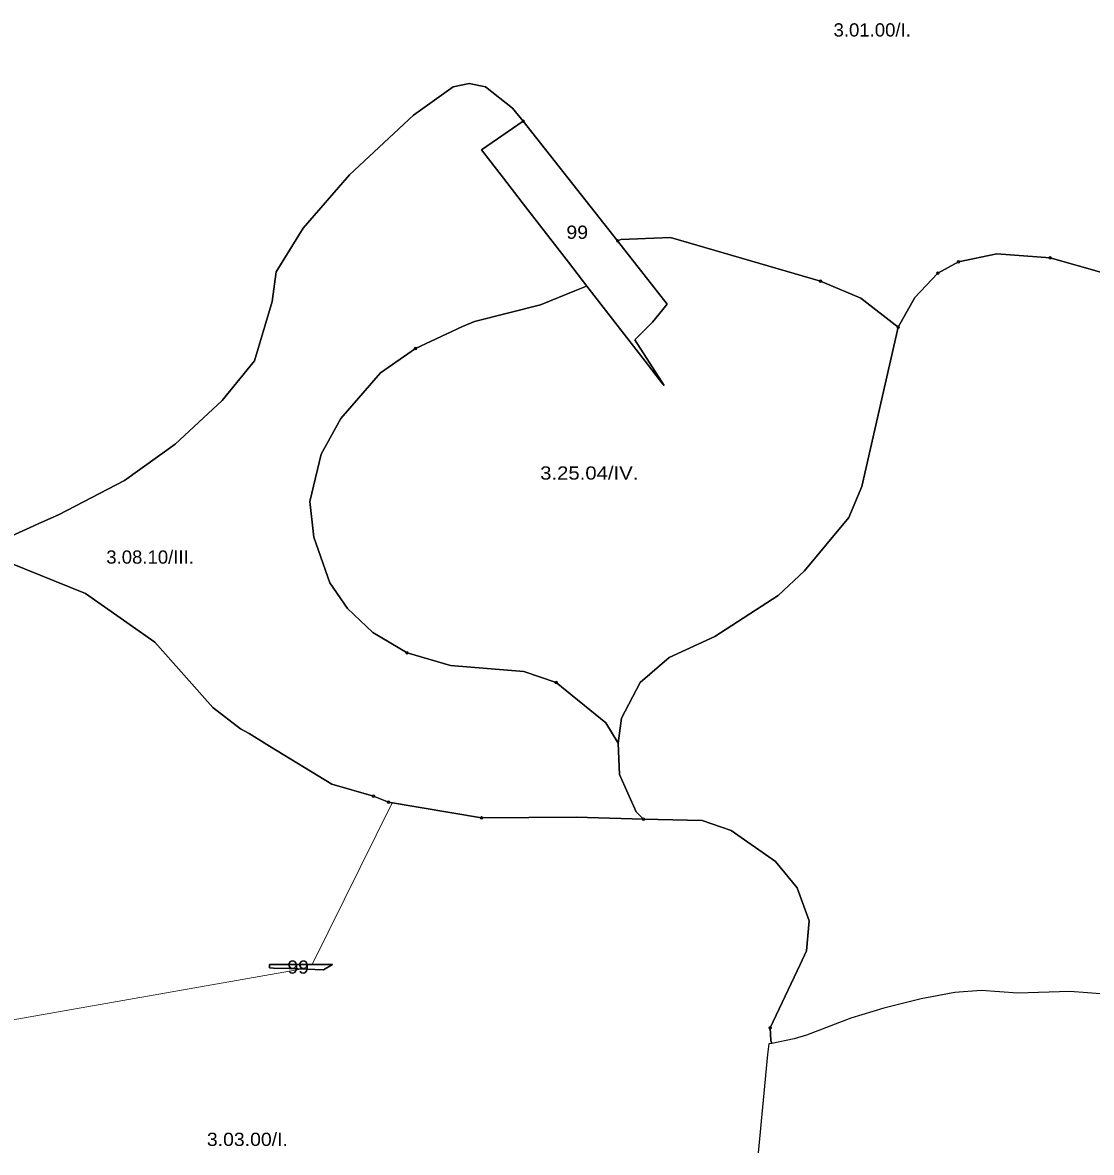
# Model space of a CAD drawing. Extents: x -650455 to -642254, y -1075222 to -1066610.
# Drawn here: x -647687 to -646878, y -1073142 to -1072287 of the extents above; entities that cross this region are included whole.
import ezdxf
from ezdxf.enums import TextEntityAlignment as Align

# ---------------------------------------------------------------- set-up
doc = ezdxf.new("R2010")
doc.units = 0
doc.header["$LTSCALE"] = 4
doc.header["$PDMODE"] = 32
doc.header["$PDSIZE"] = 2
for name, color, linetype, lineweight in [('1', 7, 'Continuous', 25), ('11', 7, 'Continuous', 13), ('13', 7, 'Continuous', 13), ('14', 7, 'Continuous', 13)]:
    doc.layers.add(name, color=color, linetype=linetype, lineweight=lineweight)
doc.layers.add('2', color=7, linetype='Continuous')

msp = doc.modelspace()

# ---------------------------------------------------------------- linework, layer by layer
at = {"layer": '1'}
for points in [[(-647639.5, -1072719.001), (-647697.5, -1072695.5), (-647728.952, -1072689.256), (-647713.137, -1072683.505), (-647698.521, -1072676.851), (-647672.5, -1072665), (-647660, -1072659.5), (-647610, -1072633.501), (-647571.5, -1072606.001), (-647536, -1072573.001), (-647511.5, -1072543), (-647500, -1072504.667), (-647498, -1072498), (-647495, -1072475.501), (-647474.5, -1072442.501), (-647439.5, -1072402.001), (-647391, -1072357), (-647361, -1072335.5), (-647349, -1072333), (-647336.5, -1072335.5), (-647316, -1072351.5), (-647308, -1072361.501)], [(-646870, -1072476.001), (-646909, -1072465), (-646949.5, -1072462), (-646978.5, -1072468.001), (-646994, -1072476.501), (-647011.5, -1072495), (-647024, -1072517.5), (-647052.5, -1072495.501), (-647083, -1072482.5), (-647196.5, -1072449.5), (-647234, -1072451.001), (-647236.5, -1072452.001), (-647308, -1072361.501), (-647316, -1072351.5), (-647336.5, -1072335.5), (-647349, -1072333), (-647361, -1072335.5), (-647391, -1072357), (-647439.5, -1072402.001), (-647474.5, -1072442.501), (-647495, -1072475.501), (-647498, -1072498), (-647500, -1072504.667), (-647511.5, -1072543), (-647536, -1072573.001), (-647571.5, -1072606.001), (-647610, -1072633.501), (-647660, -1072659.5), (-647672.5, -1072665)], [(-647308, -1072361.501), (-647339.712, -1072383.178), (-647323.06, -1072404.651), (-647306.23, -1072426.351), (-647273.75, -1072468.221), (-647259.75, -1072486.28), (-647259.98, -1072486.34), (-647269, -1072490), (-647295, -1072500.501), (-647345, -1072513.001), (-647354, -1072517.001), (-647389.5, -1072533.5), (-647416, -1072552.001), (-647446, -1072586.5), (-647461, -1072613.501), (-647469.5, -1072649.501), (-647466.5, -1072676.5), (-647454.5, -1072711.001), (-647441, -1072730.501), (-647422, -1072748.5), (-647396, -1072764.001), (-647363, -1072773.5), (-647307.5, -1072778), (-647283, -1072786.5), (-647245.5, -1072817), (-647236, -1072832.501), (-647235, -1072856.001), (-647222.5, -1072884.501), (-647217, -1072890), (-647268, -1072888.501), (-647339.5, -1072889.001), (-647410, -1072877.001), (-647421.34, -1072872.531), (-647453, -1072863.5), (-647500, -1072834.548), (-647515.5, -1072825), (-647522, -1072821.5), (-647543, -1072805.5), (-647587, -1072756.001), (-647639.5, -1072719.001)], [(-647024, -1072517.5), (-647051.5, -1072638.001), (-647061.5, -1072661.501), (-647095, -1072702.001), (-647115, -1072720.5), (-647163, -1072751.501), (-647197.5, -1072767.501), (-647219.5, -1072786.5), (-647233.5, -1072813.5), (-647236, -1072832.501), (-647245.5, -1072817), (-647283, -1072786.5), (-647307.5, -1072778), (-647363, -1072773.5), (-647396, -1072764.001), (-647422, -1072748.5), (-647441, -1072730.501), (-647454.5, -1072711.001), (-647466.5, -1072676.5), (-647469.5, -1072649.501), (-647461, -1072613.501), (-647446, -1072586.5), (-647416, -1072552.001), (-647389.5, -1072533.5), (-647354, -1072517.001), (-647345, -1072513.001), (-647295, -1072500.501), (-647269, -1072490), (-647259.98, -1072486.34), (-647259.75, -1072486.28), (-647217.32, -1072540.99), (-647215.71, -1072543.071), (-647202.22, -1072560.471), (-647201.29, -1072561.671), (-647223.5, -1072527), (-647210, -1072513.5), (-647199, -1072500.001), (-647236.5, -1072452.001), (-647234, -1072451.001), (-647196.5, -1072449.5)], [(-647196.5, -1072449.5), (-647083, -1072482.5), (-647052.5, -1072495.501), (-647024, -1072517.5)], [(-647197.5, -1072767.501), (-647163, -1072751.501), (-647115, -1072720.5), (-647095, -1072702.001), (-647061.5, -1072661.501), (-647051.5, -1072638.001), (-647024, -1072517.5), (-647011.5, -1072495), (-646994, -1072476.501), (-646978.5, -1072468.001), (-646949.5, -1072462), (-646909, -1072465), (-646870, -1072476.001), (-646796, -1072525.5), (-646755, -1072562), (-646671, -1072656.5), (-646615.5, -1072728.5), (-646581.5, -1072768.5), (-646545.5, -1072791.001), (-646519.5, -1072800.501)], [(-647672.5, -1072665), (-647698.521, -1072676.851)], [(-647904.5, -1073148.001), (-647889.5, -1073048.5), (-647885.418, -1073000), (-647881, -1072947.5), (-647868, -1072828.501), (-647861.5, -1072813), (-647845.5, -1072785), (-647801.5, -1072733.5), (-647763.5, -1072702.001), (-647731, -1072690.001), (-647728.952, -1072689.256), (-647697.5, -1072695.5), (-647639.5, -1072719.001), (-647587, -1072756.001), (-647543, -1072805.5), (-647522, -1072821.5), (-647515.5, -1072825), (-647500, -1072834.548), (-647453, -1072863.5), (-647421.34, -1072872.531), (-647410, -1072877.001), (-647339.5, -1072889.001)], [(-646867.497, -1073022.31), (-646894.212, -1073020.321), (-646933.434, -1073021.742), (-646961.287, -1073019.609), (-646981.181, -1073021.173), (-647006.761, -1073025.862), (-647034.898, -1073032.967), (-647060.05, -1073040.642), (-647093.445, -1073053.573), (-647102.824, -1073056.274), (-647119.798, -1073059.69), (-647120.5, -1073057.5), (-647121, -1073048), (-647098.436, -1073000), (-647093.5, -1072989.501), (-647091.5, -1072967), (-647100.5, -1072942.001), (-647117, -1072922.001), (-647150.5, -1072898.5), (-647172.5, -1072891), (-647217, -1072890), (-647222.5, -1072884.501), (-647235, -1072856.001), (-647236, -1072832.501), (-647233.5, -1072813.5), (-647219.5, -1072786.5), (-647197.5, -1072767.501)], [(-647339.5, -1072889.001), (-647268, -1072888.501), (-647217, -1072890)], [(-647217, -1072890), (-647172.5, -1072891), (-647150.5, -1072898.5), (-647117, -1072922.001), (-647100.5, -1072942.001), (-647091.5, -1072967), (-647093.5, -1072989.501), (-647098.436, -1073000), (-647121, -1073048), (-647120.5, -1073057.5), (-647119.798, -1073059.69), (-647121.913, -1073060.116), (-647122.941, -1073068.189), (-647130.088, -1073142.652)]]:
    msp.add_lwpolyline(points, dxfattribs=at)
for points in [[(-647236.5, -1072452.001), (-647199, -1072500.001), (-647210, -1072513.5), (-647223.5, -1072527), (-647201.29, -1072561.671), (-647202.22, -1072560.471), (-647215.71, -1072543.071), (-647217.32, -1072540.99), (-647259.75, -1072486.28), (-647273.75, -1072468.221), (-647306.23, -1072426.351), (-647323.06, -1072404.651), (-647339.712, -1072383.178), (-647308, -1072361.501)], [(-647452.469, -1073000), (-647459.21, -1073004.071), (-647485.29, -1073003.08), (-647497.2, -1073002.63), (-647500, -1073002.544), (-647500.13, -1073002.54), (-647500.097, -1073000), (-647500, -1073000)], [(-647452.469, -1073000), (-647500, -1073000), (-647500.097, -1073000), (-647500.13, -1073002.54), (-647500, -1073002.544), (-647497.2, -1073002.63), (-647485.29, -1073003.08), (-647459.21, -1073004.071)]]:
    msp.add_lwpolyline(points, close=True, dxfattribs=at)
at = {"layer": '11'}
for p, q in [((-646978.5, -1072468.001), (-646994, -1072476.501)), ((-646870, -1072476.001), (-646909, -1072465)), ((-647410, -1072877.001), (-647421.34, -1072872.531))]:
    msp.add_line(p, q, dxfattribs=at)
for points in [[(-647845.5, -1072785), (-647801.5, -1072733.5), (-647763.5, -1072702.001), (-647731, -1072690.001), (-647728.952, -1072689.256), (-647713.137, -1072683.505), (-647698.521, -1072676.851), (-647672.5, -1072665), (-647660, -1072659.5), (-647610, -1072633.501), (-647571.5, -1072606.001), (-647536, -1072573.001), (-647511.5, -1072543), (-647500, -1072504.667), (-647498, -1072498), (-647495, -1072475.501), (-647474.5, -1072442.501), (-647439.5, -1072402.001), (-647391, -1072357), (-647361, -1072335.5), (-647349, -1072333), (-647336.5, -1072335.5), (-647316, -1072351.5), (-647308, -1072361.501)], [(-647308, -1072361.501), (-647236.5, -1072452.001), (-647234, -1072451.001), (-647196.5, -1072449.5), (-647083, -1072482.5)], [(-647083, -1072482.5), (-647052.5, -1072495.501), (-647024, -1072517.5), (-647011.5, -1072495), (-646994, -1072476.501), (-646978.5, -1072468.001), (-646949.5, -1072462), (-646909, -1072465), (-646870, -1072476.001), (-646796, -1072525.5)], [(-646909, -1072465), (-646949.5, -1072462), (-646978.5, -1072468.001)], [(-646994, -1072476.501), (-647011.5, -1072495), (-647024, -1072517.5)], [(-647024, -1072517.5), (-647051.5, -1072638.001), (-647061.5, -1072661.501), (-647095, -1072702.001), (-647115, -1072720.5), (-647163, -1072751.501), (-647197.5, -1072767.501), (-647219.5, -1072786.5), (-647233.5, -1072813.5), (-647236, -1072832.501), (-647235, -1072856.001), (-647222.5, -1072884.501), (-647217, -1072890)], [(-647421.34, -1072872.531), (-647453, -1072863.5), (-647500, -1072834.548), (-647515.5, -1072825), (-647522, -1072821.5), (-647543, -1072805.5), (-647587, -1072756.001), (-647639.5, -1072719.001), (-647697.5, -1072695.5), (-647728.952, -1072689.256), (-647731, -1072690.001), (-647763.5, -1072702.001), (-647801.5, -1072733.5), (-647845.5, -1072785), (-647861.5, -1072813), (-647868, -1072828.501), (-647881, -1072947.5), (-647885.418, -1073000), (-647889.5, -1073048.5)], [(-647339.5, -1072889.001), (-647407.174, -1072877.482), (-647467.805, -1073000), (-647452.469, -1073000), (-647459.21, -1073004.071), (-647476.435, -1073003.416), (-647893.795, -1073076.991), (-647904.5, -1073148.001), (-647917.5, -1073209.501), (-647919.5, -1073256), (-647914.5, -1073287.5), (-647902, -1073313.501), (-647885, -1073332.5), (-647865, -1073347.001), (-647852.5, -1073352.5), (-647735.5, -1073384), (-647648, -1073415.501), (-647589.5, -1073433)], [(-647476.435, -1073003.416), (-647485.29, -1073003.08), (-647497.2, -1073002.63), (-647500, -1073002.544), (-647500.13, -1073002.54), (-647500.097, -1073000), (-647500, -1073000), (-647467.805, -1073000), (-647407.174, -1072877.482), (-647410, -1072877.001)], [(-647130.088, -1073142.652), (-647122.941, -1073068.189), (-647121.913, -1073060.116), (-647119.798, -1073059.69), (-647120.5, -1073057.5), (-647121, -1073048), (-647098.436, -1073000), (-647093.5, -1072989.501), (-647091.5, -1072967), (-647100.5, -1072942.001), (-647117, -1072922.001), (-647150.5, -1072898.5), (-647172.5, -1072891), (-647217, -1072890), (-647268, -1072888.501), (-647339.5, -1072889.001)], [(-647217, -1072890), (-647172.5, -1072891), (-647150.5, -1072898.5), (-647117, -1072922.001), (-647100.5, -1072942.001), (-647091.5, -1072967), (-647093.5, -1072989.501), (-647098.436, -1073000), (-647121, -1073048)], [(-647889.5, -1073048.5), (-647893.795, -1073076.991), (-647476.435, -1073003.416)], [(-647121, -1073048), (-647120.5, -1073057.5), (-647119.798, -1073059.69), (-647102.824, -1073056.274), (-647093.445, -1073053.573), (-647060.05, -1073040.642), (-647034.898, -1073032.967), (-647006.761, -1073025.862), (-646981.181, -1073021.173), (-646961.287, -1073019.609), (-646933.434, -1073021.742), (-646894.212, -1073020.321), (-646867.497, -1073022.31)]]:
    msp.add_lwpolyline(points, dxfattribs=at)
for p in [(-647308, -1072361.501), (-646909, -1072465), (-646978.5, -1072468.001), (-646994, -1072476.501), (-647083, -1072482.5), (-647024, -1072517.5), (-647421.34, -1072872.531), (-647410, -1072877.001), (-647339.5, -1072889.001), (-647217, -1072890), (-647121, -1073048)]:
    msp.add_point(p, dxfattribs=at)
at = {"layer": '13'}
for points in [[(-647308, -1072361.501), (-647316, -1072351.5), (-647336.5, -1072335.5), (-647349, -1072333), (-647361, -1072335.5), (-647391, -1072357), (-647439.5, -1072402.001), (-647474.5, -1072442.501), (-647495, -1072475.501), (-647498, -1072498), (-647500, -1072504.667), (-647511.5, -1072543), (-647536, -1072573.001), (-647571.5, -1072606.001), (-647610, -1072633.501), (-647660, -1072659.5), (-647672.5, -1072665), (-647698.521, -1072676.851), (-647713.137, -1072683.505), (-647728.952, -1072689.256), (-647697.5, -1072695.5), (-647639.5, -1072719.001), (-647587, -1072756.001)], [(-647389.5, -1072533.5), (-647354, -1072517.001), (-647345, -1072513.001), (-647295, -1072500.501), (-647269, -1072490), (-647259.98, -1072486.34), (-647259.75, -1072486.28), (-647273.75, -1072468.221), (-647306.23, -1072426.351), (-647323.06, -1072404.651), (-647339.712, -1072383.178), (-647308, -1072361.501)], [(-647283, -1072786.5), (-647307.5, -1072778), (-647363, -1072773.5), (-647396, -1072764.001), (-647422, -1072748.5), (-647441, -1072730.501), (-647454.5, -1072711.001), (-647466.5, -1072676.5), (-647469.5, -1072649.501), (-647461, -1072613.501), (-647446, -1072586.5), (-647416, -1072552.001), (-647389.5, -1072533.5)], [(-647587, -1072756.001), (-647543, -1072805.5), (-647522, -1072821.5), (-647515.5, -1072825), (-647500, -1072834.548), (-647453, -1072863.5), (-647421.34, -1072872.531), (-647410, -1072877.001), (-647339.5, -1072889.001), (-647268, -1072888.501), (-647217, -1072890), (-647222.5, -1072884.501), (-647235, -1072856.001), (-647236, -1072832.501), (-647245.5, -1072817), (-647283, -1072786.5)]]:
    msp.add_lwpolyline(points, dxfattribs=at)
for p in [(-647308, -1072361.501), (-647389.5, -1072533.5), (-647283, -1072786.5)]:
    msp.add_point(p, dxfattribs=at)
at = {"layer": '14'}
for points in [[(-647236.5, -1072452.001), (-647199, -1072500.001), (-647210, -1072513.5), (-647223.5, -1072527), (-647201.29, -1072561.671), (-647202.22, -1072560.471), (-647215.71, -1072543.071), (-647217.32, -1072540.99), (-647259.75, -1072486.28), (-647259.98, -1072486.34), (-647269, -1072490), (-647295, -1072500.501), (-647345, -1072513.001), (-647354, -1072517.001), (-647389.5, -1072533.5), (-647416, -1072552.001), (-647446, -1072586.5), (-647461, -1072613.501), (-647469.5, -1072649.501), (-647466.5, -1072676.5), (-647454.5, -1072711.001), (-647441, -1072730.501), (-647422, -1072748.5), (-647396, -1072764.001)], [(-647283, -1072786.5), (-647245.5, -1072817), (-647236, -1072832.501), (-647233.5, -1072813.5), (-647219.5, -1072786.5), (-647197.5, -1072767.501), (-647163, -1072751.501), (-647115, -1072720.5), (-647095, -1072702.001), (-647061.5, -1072661.501), (-647051.5, -1072638.001), (-647024, -1072517.5), (-647052.5, -1072495.501), (-647083, -1072482.5), (-647196.5, -1072449.5), (-647234, -1072451.001), (-647236.5, -1072452.001)], [(-647396, -1072764.001), (-647363, -1072773.5), (-647307.5, -1072778), (-647283, -1072786.5)]]:
    msp.add_lwpolyline(points, dxfattribs=at)
for p in [(-647236.5, -1072452.001), (-647396, -1072764.001), (-647283, -1072786.5)]:
    msp.add_point(p, dxfattribs=at)

# ---------------------------------------------------------------- texts
at = {"layer": '2'}
for s, width, p in [('3.01.00/I.', 1.05, (-647043.757, -1072297.321)), ('99', 1.1, (-647267.127, -1072450.514)), ('3.25.04/IV.', 1.15, (-647257.99, -1072632.827)), ('3.08.10/III.', 1.05, (-647590.541, -1072696.467)), ('99', 1.1, (-647478.431, -1073006.911)), ('3.03.00/I.', 1.1, (-647516.849, -1073137.354))]:
    msp.add_text(s, height=10, dxfattribs=dict(at, width=width)).set_placement(p, align=Align.CENTER)

doc.saveas('drawing.dxf')
